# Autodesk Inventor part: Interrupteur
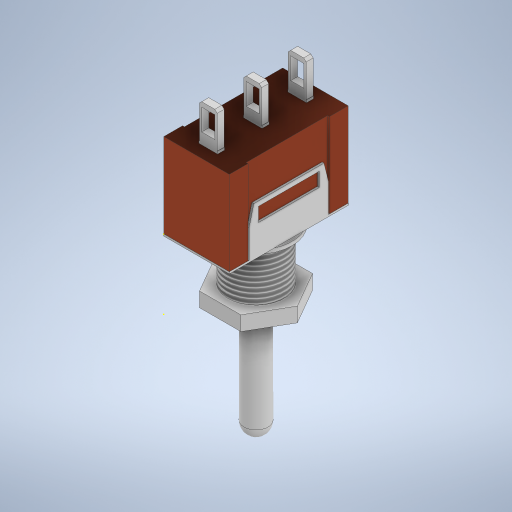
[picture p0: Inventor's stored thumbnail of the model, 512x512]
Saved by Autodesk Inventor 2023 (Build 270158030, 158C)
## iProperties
Created: 2022-12
Part Number: Interrupteur
Material: Générique
Document SubType Name: Modeling
Designer: ecuenot
Density: 1 g/cm^3
Appearance: Par défaut
Author: ecuenot
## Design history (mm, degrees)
sketch "Esquisse1"
  geometry: L1 (0, 0)-(9, 0); L2 (9, 0)-(9, -12.7); L3 (9, -12.7)-(0, -12.7); L4 (0, -12.7)-(0, 0)
  constraints: 8 end point, 2 parallel, 1 horizontal, 1 perpendicular
  dimensions: "d0" = 9 distance of L2.end L3.end; "d1" = 12.7 distance of L1.end L2.end
extrude "Extrusion1" new body sketch "Esquisse1" distance "d2" = 7; taper "d3" = 0 deg
sketch "Esquisse2"
  geometry: L1 (2, -1.222)-(10.7, -1.222); L2 (10.7, -1.222)-(10.7, 10.024); L3 (10.7, 10.024)-(2, 10.024); L4 (2, 10.024)-(2, -1.222); L5 (0, 9)-(0, 0) reference; L6 (12.7, 0)-(12.7, 9) reference
  constraints: 8 end point, 2 parallel, 1 horizontal, 1 perpendicular
  dimensions: "d4" = 2 distance between parallel lines of L4 L5; "d5" = 2 distance between parallel lines of L6 L2
extrude "Extrusion2" cut sketch "Esquisse2" distance "d6" = 0.2; taper "d7" = 0 deg
sketch "Esquisse3"
  geometry: L1 (-2, -2.975)-(-10.7, -2.975); L2 (-10.7, -2.975)-(-10.7, 12.184); L3 (-10.7, 12.184)-(-2, 12.184); L4 (-2, 12.184)-(-2, -2.975); L5 (0, 9)-(0, 0) reference; L6 (-12.7, 0)-(-12.7, 9) reference
  constraints: 8 end point, 2 parallel, 1 horizontal, 1 perpendicular
  dimensions: "d8" = 2 distance between parallel lines of L5 L4; "d9" = 2 distance between parallel lines of L6 L2
extrude "Extrusion3" cut sketch "Esquisse3" distance "d10" = 0.2; taper "d11" = 0 deg
sketch "Esquisse4"
  geometry: L1 (7.01, -0.01)-(-0.01, -0.01); L2 (-0.01, -0.01)-(-0.01, 12.71); L3 (-0.01, 12.71)-(7.01, 12.71); L4 (7.01, 12.71)-(7.01, -0.01); L5 (0, 0)-(7, 0) reference; L6 (0, 2)-(0, 0) reference; L7 (7, 2)-(7, 0) reference; L8 (0, 12.7)-(7, 12.7) reference
  constraints: 8 end point, 2 parallel, 1 horizontal, 1 perpendicular
  dimensions: "d12" = 0.01 distance between parallel lines of L1 L5; "d13" = 0.01 distance between parallel lines of L2 L6; "d14" = 0.01 distance between parallel lines of L7 L4; "d15" = 0.01 distance between parallel lines of L8 L3
extrude "Extrusion4" join sketch "Esquisse4" distance "d16" = 0.2; taper "d17" = 0 deg
sketch "Esquisse6"
  geometry: L1 (7.01, 0.01)-(7.01, -12.71) reference; L2 (7.01, -2.1)-(6.81, -2.1); L3 (6.81, -2.1)-(6.81, -10.6); L4 (6.81, -10.6)-(7.01, -10.6); L5 (7.01, -10.6)-(7.01, -2.1); L6 (6.8, -2)-(7, -2) reference; L7 (7, -10.7)-(6.8, -10.7) reference; L8 (6.8, -10.7)-(6.8, -2) reference; 8 further points
  constraints: 8 end point, 6 midpoint, 2 parallel, 1 horizontal, 1 perpendicular, 1 point on line
  dimensions: "d23" = 0.1 vertical distance of point (6.91, -2.1) point (6.9, -2); "d24" = 0.1 vertical distance of point (6.91, -10.6) point (6.9, -10.7); "d26" = 0.2 distance of point (6.81, -6.35) point (7.01, -6.35)
extrude "Extrusion6" join sketch "Esquisse6" distance "d27" = 5; taper "d28" = 0 deg
chamfer "Chanfrein1" distance "d29" = 0.5; stored, may be unused: second distance "d30" = 2, angle "d31" = 45 deg
chamfer "Chanfrein2" distance "d32" = 0.5; stored, may be unused: second distance "d33" = 2, angle "d34" = 45 deg
sketch "Esquisse7"
  geometry: 1 further point
sketch "Esquisse8"
  geometry: L1 (-0.01, -12.71)-(-0.01, 0.01) reference; L2 (-0.01, -10.6)-(0.19, -10.6); L3 (0.19, -10.6)-(0.19, -2.1); L4 (0.19, -2.1)-(-0.01, -2.1); L5 (-0.01, -2.1)-(-0.01, -10.6); L6 (0.2, -10.7)-(0, -10.7) reference; L7 (0, -2)-(0.2, -2) reference; 6 further points
  constraints: 8 end point, 4 midpoint, 2 parallel, 1 horizontal, 1 perpendicular, 1 point on line
  dimensions: "d35" = 0.2 distance between parallel lines of L3 L1; "d36" = 0.1 vertical distance of point (0.1, -10.7) point (0.09, -10.6); "d37" = 0.1 vertical distance of point (0.1, -2) point (0.09, -2.1)
extrude "Extrusion7" join sketch "Esquisse8" distance "d38" = 5; taper "d39" = 0 deg
chamfer "Chanfrein3" distance "d40" = 0.5; stored, may be unused: second distance "d41" = 2, angle "d42" = 45 deg
chamfer "Chanfrein4" distance "d43" = 0.5; stored, may be unused: second distance "d44" = 2, angle "d45" = 45 deg
sketch "Esquisse9"
  geometry: L1 (9.61, 3.2)-(3.11, 3.2); L2 (3.11, 3.2)-(3.11, 4.7); L3 (3.11, 4.7)-(9.61, 4.7); L4 (9.61, 4.7)-(9.61, 3.2); L5 (10.61, 0.2)-(10.61, 3.2) reference; L6 (2.11, 0.2)-(2.11, 3.2) reference; 1 further point
  constraints: 8 end point, 2 parallel, 1 horizontal, 1 perpendicular
  dimensions: "d46" = 1.5 distance of L1.end L2.end; "d47" = 1 distance between parallel lines of L4 L5; "d48" = 1 distance between parallel lines of L6 L2
extrude "Extrusion8" cut sketch "Esquisse9" stored distance "d49" = 5; taper "d50" = 0 deg
sketch "Esquisse10"
  geometry: L1 (9.61, 3.2)-(3.11, 3.2) reference; L2 (9.61, 4.7)-(3.11, 4.7) reference; L3 (9.61, 3.2)-(3.11, 3.2); L4 (3.11, 3.2)-(3.11, 4.7); L5 (3.11, 4.7)-(9.61, 4.7); L6 (9.61, 4.7)-(9.61, 3.2); 3 further points
  constraints: 8 end point, 2 parallel, 1 horizontal, 1 perpendicular
extrude "Extrusion9" cut sketch "Esquisse10" stored distance "d51" = 10; taper "d52" = 0 deg
sketch "Esquisse11"
  geometry: L1 (2.5, 1.25)-(4.5, 1.25); L2 (4.5, 1.25)-(4.5, 2); L3 (4.5, 2)-(2.5, 2); L4 (2.5, 2)-(2.5, 1.25); L5 (0, 2)-(0, 0) reference; L6 (0, 0)-(7, 0) reference; 1 further point
  constraints: 8 end point, 2 parallel, 1 horizontal, 1 midpoint, 1 perpendicular
  dimensions: "d53" = 2 distance of L3.end L2.end; "d54" = 0.75 distance of L2.end L1.end; "d55" = 2.5 distance from line of point (2.5, 1.625) L5; "d56" = 1.25 distance between parallel lines of L6 L1
extrude "Extrusion10" join sketch "Esquisse11" distance "d57" = 0.25; taper "d58" = 0 deg
sketch "Esquisse12"
  geometry: L1 (4.5, 1.25)-(2.5, 1.25) reference; L2 (2.5, 2)-(4.5, 2) reference; L3 (2.55, 1.25)-(4.45, 1.25); L4 (4.45, 1.25)-(4.45, 2); L5 (4.45, 2)-(2.55, 2); L6 (2.55, 2)-(2.55, 1.25); L7 (2.5, 2)-(2.5, 1.25) reference; L8 (4.5, 1.25)-(4.5, 2) reference; 6 further points
  constraints: 8 end point, 3 midpoint, 2 parallel, 2 point on line, 1 horizontal, 1 perpendicular
  dimensions: "d59" = 0.05 distance from line of L7 point (2.55, 1.625); "d60" = 0.05 distance of point (4.5, 1.625) point (4.45, 1.625)
extrude "Extrusion11" join sketch "Esquisse12" distance "d61" = 3.75; taper "d62" = 0 deg
chamfer "Chanfrein5" distance "d63" = 0.25; stored, may be unused: second distance "d64" = 2, angle "d65" = 45 deg
chamfer "Chanfrein6" distance "d66" = 0.25; stored, may be unused: second distance "d67" = 2, angle "d68" = 45 deg
sketch "Esquisse13"
  geometry: L1 (0.3, 3.5)-(1.7, 3.5); L2 (1.7, 3.5)-(1.7, 1.202); L3 (1.7, 1.202)-(0.3, 1.202); L4 (0.3, 1.202)-(0.3, 3.5); L5 (0.3, 4)-(1.7, 4) reference; L6 (1.95, 0.25)-(1.95, 3.75) reference; L7 (0.05, 0.25)-(0.05, 3.75) reference; 3 further points
  constraints: 8 end point, 2 midpoint, 2 parallel, 1 horizontal, 1 perpendicular
  dimensions: "d69" = 0.5 distance of point (1, 4) point (1, 3.5); "d70" = 0.25 distance between parallel lines of L6 L2; "d71" = 0.25 distance between parallel lines of L7 L4
extrude "Extrusion12" cut sketch "Esquisse13" stored distance "d72" = 3.75; taper "d73" = 0 deg
pattern_linear "Réseau rectangulaire1" dims "d76" = 4.75
sketch "Esquisse14"
  geometry: L1 (0, 0)-(7, 0) reference; L2 (0, 0)-(0, 2) reference; L3 (0, 12.7)-(7, 12.7) reference; C1 r 3.85 at (3.5, 6.35)
  constraints: 1 centre point
  dimensions: "d77" = 7.7 diameter of C1
extrude "Extrusion13" join sketch "Esquisse14" distance "d78" = 0.4; taper "d79" = 0 deg
sketch "Esquisse15"
  geometry: C1 r 3 at (0, 0); 1 further point
  constraints: 1 centre point
  dimensions: "d80" = 6 diameter of C1
extrude "Extrusion14" join sketch "Esquisse15" distance "d81" = 7.6; taper "d82" = 0 deg
chamfer "Chanfrein7" distance "d83" = 0.25; stored, may be unused: second distance "d84" = 2, angle "d85" = 45 deg
sketch "Esquisse16"
  geometry: C1 r 2.125 at (0, 0); 1 further point
  constraints: 1 centre point
  dimensions: "d86" = 4.25 diameter of C1
extrude "Extrusion15" cut sketch "Esquisse16" distance "d87" = 2.5; taper "d88" = 0 deg
node "Plan de construction1"
sketch "Esquisse18"
  geometry: 1 further point
sketch "Esquisse19"
  geometry: L1 (-4.419, 0)-(-2.209, 3.827); L2 (-2.209, 3.827)-(2.209, 3.827); L3 (2.209, 3.827)-(4.419, 0); L4 (4.419, 0)-(2.209, -3.827); L5 (2.209, -3.827)-(-2.209, -3.827); L6 (-2.209, -3.827)-(-4.419, 0); 2 further points
  constraints: 12 end point, 13 other
extrude "Extrusion16" join sketch "Esquisse19" distance "d90" = 1.55; taper "d91" = 0 deg
node "Axe de construction1"
sketch "Esquisse21"
  geometry: C1 r 1.3 at (0, 0); 1 further point
  constraints: 1 centre point
  dimensions: "d94" = 2.6 diameter of C1
extrude "Extrusion17" join sketch "Esquisse21" distance "d95" = 12.5; taper "d96" = 0 deg
fillet "Congé1" dims "d97" = 1.3
feature "Filetage1" dims "d98" = 5.3, "d99" = 0
feature "Filetage2" dims "d100" = 0.5, "d101" = 0
node "Solide1"
other parameters: "d89" = -0.75
